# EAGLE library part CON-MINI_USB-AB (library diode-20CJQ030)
Various Mini-USB Type AB Connectors
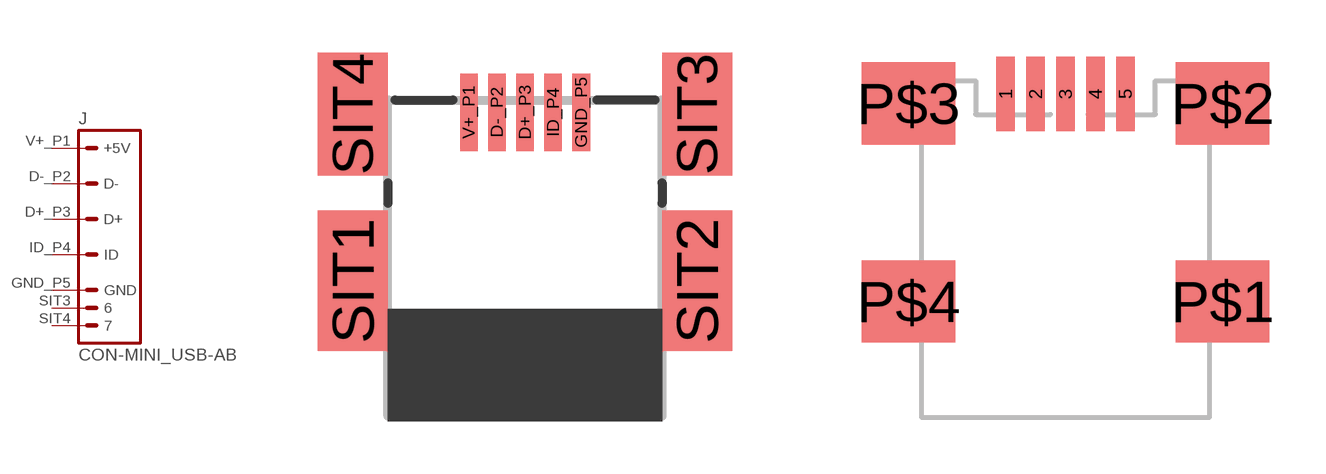
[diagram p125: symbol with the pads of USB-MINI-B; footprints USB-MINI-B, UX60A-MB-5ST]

Designator prefix J

## CON-MINI_USB-AB-1  [USB-MINI-B]
D+_P3  D+  pas
D-_P2  D-  pas
GND_P5  GND  pas
ID_P4  ID  pas
SIT3  6  pas
SIT4  7  pas
V+_P1  +5V  pas

## CON-MINI_USB-AB-2  [UX60A-MB-5ST]
1  +5V  pas
2  D-  pas
3  D+  pas
4  ID  pas
5  GND  pas
P$2  6  pas
P$3  7  pas

## CON-MINI_USB-AB-3  [UX60-MB-5ST]
Pads as for UX60A-MB-5ST

## Footprint USB-MINI-B (pad centres in mm)
MOLEX USB type mini-B surface mount connector digikey part#: WM2499CT-ND $2.38CAN each
smd 0.5 x 2.2: D+_P3 0,3.5; D-_P2 -0.8,3.5; GND_P5 1.6,3.5; ID_P4 0.8,3.5; V+_P1 -1.6,3.5
smd 2 x 4: SIT1 -4.9,-1.3; SIT2 4.9,-1.3
smd 2 x 3.5: SIT3 4.9,3.45; SIT4 -4.9,3.45

## Footprint UX60A-MB-5ST (pad centres in mm)
Hirose's UX Series Mini-USB-Type A/B Connector Metal Shield SMT Type Without Positioning Post Features: 1. Certified to perform as required in USB 2.0 Standard Tested and certified by USB Association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
smd 0.5 x 2: 1 -5.45,-1.05; 2 -4.65,-1.05; 3 -3.85,-1.05; 4 -3.05,-1.05; 5 -2.25,-1.05
smd 2.5 x 2.2: P$1 0.35,-6.6; P$2 0.35,-1.3; P$3 -8.05,-1.3; P$4 -8.05,-6.6

## Footprint UX60-MB-5ST (pad centres in mm)
Hirose's UX Series Mini-USB-Type A/B Connector Metal Shield SMT Type With Positioning Post Features: 1. Certified to perform as required in USB 2.0 Standard Tested and certified by USB Association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
smd 0.5 x 2: 1 -1.6,2.25; 2 -0.8,2.25; 3 0,2.25; 4 0.8,2.25; 5 1.6,2.25
smd 2.5 x 2.2: P$1 4.2,-3.3; P$2 4.2,2; P$3 -4.2,2; P$4 -4.2,-3.3
hole 0.9 at -1.75,0
hole 0.9 at 1.75,0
